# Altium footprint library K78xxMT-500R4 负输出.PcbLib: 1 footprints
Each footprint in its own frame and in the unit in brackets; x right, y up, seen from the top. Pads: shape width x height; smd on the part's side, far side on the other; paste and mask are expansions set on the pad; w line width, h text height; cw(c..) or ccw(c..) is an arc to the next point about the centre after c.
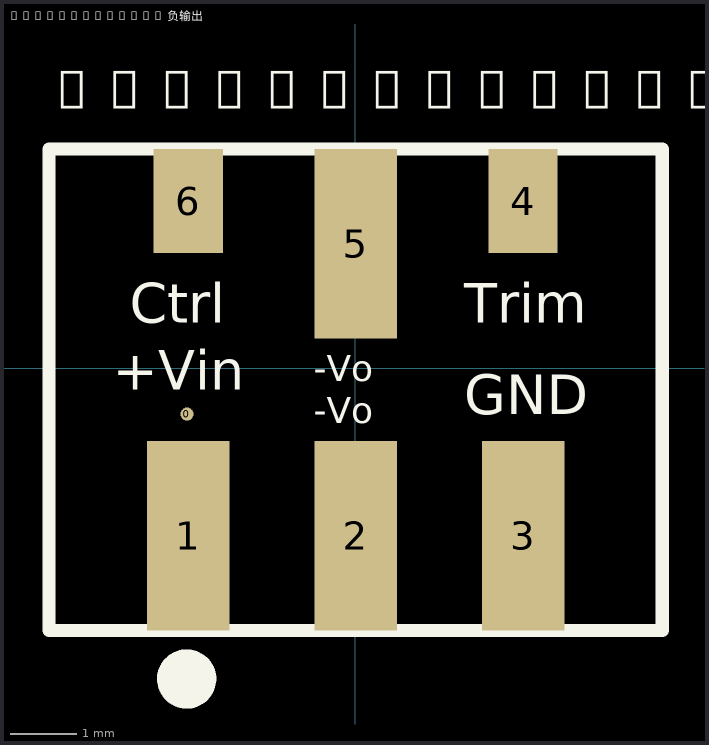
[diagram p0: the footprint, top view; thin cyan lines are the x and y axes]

## K78xxMT-500R4 负输出 [mm]
pads (7):
  round 0.2 smd mask+0.1: 0(-2.549,-0.691)
  rect 1.25x2.87 smd mask+0.102: 1(-2.531,-2.537) 2(0.009,-2.537) 3(2.549,-2.537) 5(0.009,1.893)
  rect 1.05x1.58 smd mask+0.102: 4(2.549,2.538) 6(-2.531,2.538)
Top Overlay:
  lines w0.2: -4.641,-3.972 4.659,-3.972 4.659,3.328 -4.641,3.328 -4.641,-3.972
  lines w0.5: -2.364,-4.773 cw(c-2.554,-4.71) -2.355,-4.735
  text "-Vo" at -0.626,-0.195 h0.4
  text "K78xxMT-500R4 负输出" at -4.69,3.742 h1
  text "+Vin" at -3.674,-0.322 h0.6
  text "-Vo" at -0.626,-0.83 h0.4
  text "GND" at 1.66,-0.691 h0.6
  text "Trim" at 1.66,0.694 h0.6
  text "Ctrl" at -3.42,0.694 h0.6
